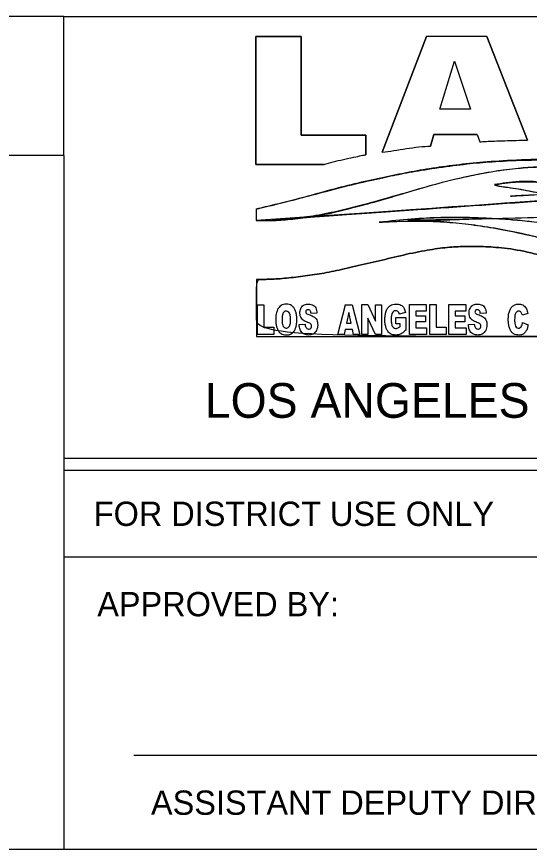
# Model space of a CAD drawing. Extents: x 837 to 1117, y 1316 to 1424.
# Drawn here: x 867.119 to 868.598, y 1399.74 to 1402.14 of the extents above; entities that cross this region are included whole.
import ezdxf

# ---------------------------------------------------------------- set-up
doc = ezdxf.new("R2010")
doc.units = 0
doc.layers.add('BASEMAP', color=7, linetype='Continuous')
doc.layers.add('LLINES', color=7, linetype='Continuous')

# ---------------------------------------------------------------- blocks, each defined once
blk = doc.blocks.new('_U1')
for p, q in [((-1.4473, 0.5842), (-1.6244, 0.5842)), ((-1.6244, 0.5842), (-1.6244, 0.0828)), ((-1.4473, 0.1969), (-1.4473, 0.5842)), ((-1.1295, 0.1307), (-0.9557, 0.5839)), ((-0.9557, 0.5839), (-1.1295, 0.1307)), ((-0.7201, 0.5839), (-0.9557, 0.5839)), ((-0.7201, 0.5839), (-0.5605, 0.1781)), ((-0.5605, 0.1781), (-0.7201, 0.5839)), ((-1.1937, 0.1969), (-1.4473, 0.1969)), ((-1.1937, 0.121), (-1.1937, 0.1969)), ((-0.9275, 0.1996), (-0.9412, 0.155)), ((-0.9412, 0.155), (-0.9275, 0.1996)), ((-0.7577, 0.1996), (-0.9275, 0.1996)), ((-0.9275, 0.1996), (-0.7577, 0.1996)), ((-0.7577, 0.1996), (-0.7467, 0.1714)), ((-0.7577, 0.1996), (-0.7467, 0.1714)), ((-1.6244, 0.0828), (-1.3574, 0.0828)), ((-1.6228, -0.0919), (-1.6228, -0.1365)), ((-1.6228, -0.0919), (-1.6228, -0.1365))]:
    blk.add_line(p, q)
for points in [[(-1.3574, 0.0828), (-1.6244, 0.0828), (-1.6244, 0.5842), (-1.4473, 0.5842), (-1.4473, 0.1969), (-1.1937, 0.1969), (-1.1937, 0.121)], [(-0.904, 0.2994), (-0.8461, 0.4865), (-0.7835, 0.2994), (-0.904, 0.2994)]]:
    blk.add_lwpolyline(points)
blk.add_lwpolyline([(-0.7835, 0.2994), (-0.904, 0.2994), (-0.8461, 0.4865)], close=True)
for points in [[(-0.7467, 0.1714), (-0.7409, 0.1718), (-0.7233, 0.1732), (-0.6924, 0.1746), (-0.6499, 0.1757), (-0.6055, 0.1772), (-0.5744, 0.1778), (-0.5605, 0.1781)], [(-0.7467, 0.1714), (-0.7409, 0.1718), (-0.7233, 0.1732), (-0.6924, 0.1746), (-0.6499, 0.1757), (-0.6055, 0.1772), (-0.5744, 0.1778), (-0.5605, 0.1781)], [(-1.1295, 0.1307), (-1.1149, 0.1326), (-1.0853, 0.1364), (-1.0345, 0.1451), (-0.9863, 0.1518), (-0.9528, 0.1542), (-0.9412, 0.155)], [(-1.1295, 0.1307), (-1.1149, 0.1326), (-1.0853, 0.1364), (-1.0345, 0.1451), (-0.9863, 0.1518), (-0.9528, 0.1542), (-0.9412, 0.155)], [(0.862, 0.0351), (0.8144, 0.0286), (0.7268, 0.0166), (0.5878, 0.0117), (0.4579, 0.0164), (0.3153, 0.0281), (0.181, 0.0458), (0.0233, 0.0686), (-0.1285, 0.0898), (-0.3136, 0.1007), (-0.4878, 0.1049), (-0.6455, 0.0979), (-0.7628, 0.0899), (-0.868, 0.0773), (-0.9701, 0.0628), (-1.064, 0.0445), (-1.1579, 0.0251), (-1.2638, 0.0013), (-1.3727, -0.0283), (-1.4702, -0.0549), (-1.5507, -0.0749), (-1.6006, -0.0866), (-1.6228, -0.0919)], [(-1.6228, -0.0919), (-1.5561, -0.0761), (-1.4734, -0.0554), (-1.3817, -0.0308), (-1.2628, 0.0006), (-1.1454, 0.0275), (-1.0649, 0.0442), (-0.9814, 0.06), (-0.8629, 0.0775), (-0.7589, 0.0894), (-0.6661, 0.0962), (-0.5111, 0.1024), (-0.2859, 0.0985), (-0.1443, 0.0891), (0.0432, 0.0657), (0.1706, 0.0476), (0.3298, 0.0278), (0.4464, 0.0181), (0.5981, 0.0133), (0.7189, 0.0181), (0.862, 0.0351), (-1.6228, -0.0919), (0.862, 0.0351)], [(-1.3574, 0.0828), (-1.3469, 0.0858), (-1.3224, 0.0927), (-1.281, 0.1027), (-1.24, 0.1114), (-1.2103, 0.1177), (-1.1971, 0.1204), (-1.1937, 0.121)], [(-1.3574, 0.0828), (-1.3469, 0.0858), (-1.3224, 0.0927), (-1.281, 0.1027), (-1.24, 0.1114), (-1.2103, 0.1177), (-1.1971, 0.1204), (-1.1937, 0.121)], [(-0.6893, 0.0039), (-0.6489, 0.0103), (-0.5954, 0.0158), (-0.5366, 0.0158), (-0.4643, 0.0069), (-0.3397, -0.01), (-0.2145, -0.0352), (-0.1206, -0.0545), (-0.0156, -0.0758), (0.0777, -0.0926), (0.156, -0.104), (0.2356, -0.1139), (0.3133, -0.1193), (0.4328, -0.1193), (0.5003, -0.1128), (0.5495, -0.1064), (0.591, -0.0996), (0.6293, -0.0912), (0.6734, -0.0739), (0.7303, -0.0551), (0.7937, -0.0344), (0.8668, -0.0105), (0.9177, 0.0048), (0.9599, 0.0174), (1.0152, 0.0322), (1.0666, 0.0451), (1.1275, 0.0585), (1.1733, 0.0677), (1.2254, 0.0756), (1.2908, 0.0827), (1.363, 0.09), (1.4273, 0.0957), (1.5059, 0.1008), (1.5711, 0.1059), (1.6246, 0.1096), (-0.6893, 0.0039), (1.6246, 0.1096)], [(1.6246, 0.1096), (1.6067, 0.1084), (1.5672, 0.1057), (1.5015, 0.1001), (1.432, 0.0965), (1.3604, 0.0899), (1.2931, 0.0829), (1.2297, 0.0766), (1.1752, 0.0686), (1.1224, 0.0574), (1.0695, 0.0462), (1.0138, 0.0317), (0.964, 0.0191), (0.9148, 0.0038), (0.8591, -0.0125), (0.797, -0.0334), (0.7326, -0.0549), (0.6768, -0.071), (0.6325, -0.0922), (0.59, -0.0998), (0.547, -0.107), (0.4943, -0.1137), (0.4157, -0.1221), (0.3271, -0.1207), (0.2347, -0.1148), (0.1563, -0.1041), (0.0725, -0.0924), (-0.0197, -0.0754), (-0.1169, -0.0551), (-0.225, -0.0335), (-0.3386, -0.0075), (-0.4469, 0.0035), (-0.5318, 0.0173), (-0.5938, 0.0168), (-0.6447, 0.0114), (-0.6759, 0.0062), (-0.6893, 0.0039)], [(-1.6228, -0.1365), (-1.599, -0.1369), (-1.555, -0.1377), (-1.4818, -0.1315), (-1.3989, -0.1209), (-1.3107, -0.1036), (-1.2241, -0.0808), (-1.1248, -0.0549), (-1.0062, -0.0178), (-0.8775, 0.0183), (-0.754, 0.0461), (-0.6492, 0.0637), (-0.5652, 0.0707), (-0.5035, 0.0751), (-0.4404, 0.0651), (-0.3485, 0.0503), (-0.224, 0.0304), (-0.1005, 0.0101), (0.0189, -0.0072), (0.1408, -0.0203), (0.2859, -0.0336), (0.4577, -0.0356), (0.6419, -0.0205), (0.7839, 0.0038), (0.8533, 0.0316), (0.862, 0.0351)], [(0.862, 0.0351), (0.8359, 0.0249), (0.6443, -0.0172), (0.4416, -0.0333), (0.286, -0.0316), (0.1309, -0.019), (0.0059, -0.0049), (-0.0795, 0.0072), (-0.2275, 0.0308), (-0.3651, 0.053), (-0.4528, 0.067), (-0.5039, 0.0732), (-0.5544, 0.0714), (-0.6368, 0.0638), (-0.7552, 0.0447), (-0.8679, 0.0195), (-1.007, -0.0188), (-1.1422, -0.0589), (-1.2268, -0.0815), (-1.3034, -0.1009), (-1.4037, -0.1206), (-1.4909, -0.1319), (-1.5515, -0.1365), (-1.6228, -0.1365), (0.862, 0.0351), (-1.6228, -0.1365)], [(-0.6893, 0.0039), (-0.6847, 0.0019), (-0.6743, -0.0027), (-0.6498, -0.0043), (-0.6171, -0.0094), (-0.5747, -0.016), (-0.5259, -0.0263), (-0.4758, -0.0365), (-0.4159, -0.0519), (-0.3581, -0.0657), (-0.2959, -0.0827), (-0.2438, -0.0953), (-0.1863, -0.1087), (-0.1368, -0.1211), (-0.0804, -0.1309), (-0.0319, -0.1418), (0.026, -0.1468), (0.0807, -0.1566), (0.145, -0.1589), (0.2056, -0.1626), (0.2726, -0.1588), (0.3301, -0.1567), (0.3834, -0.1527), (0.4207, -0.1475), (0.456, -0.1427), (0.4886, -0.1369), (0.5244, -0.1311), (0.5679, -0.1216), (0.6186, -0.1112), (0.6718, -0.098), (0.7242, -0.0877), (0.7752, -0.0766), (0.8307, -0.0636), (0.8817, -0.055), (0.9374, -0.0427), (0.9902, -0.0333), (1.0443, -0.0246), (1.0877, -0.0167), (1.1288, -0.0095), (1.1766, -0.0051), (1.2328, 0.002), (1.2932, 0.0072), (1.3499, 0.0118), (1.4167, 0.0153), (1.4938, 0.0159), (1.5658, 0.0229), (1.608, 0.0224), (1.6213, 0.0223)], [(-0.6893, 0.0039), (-0.6753, -0.0015), (-0.6567, -0.0041), (-0.618, -0.0092), (-0.5766, -0.016), (-0.53, -0.0254), (-0.4712, -0.038), (-0.4267, -0.049), (-0.3498, -0.0682), (-0.2983, -0.0818), (-0.2391, -0.0964), (-0.1939, -0.107), (-0.1258, -0.1227), (-0.0898, -0.1295), (-0.0257, -0.1414), (0.0207, -0.1469), (0.0825, -0.1553), (0.1398, -0.1589), (0.2126, -0.1613), (0.2644, -0.1594), (0.3408, -0.1557), (0.3849, -0.1521), (0.4239, -0.1471), (0.4531, -0.1429), (0.4908, -0.1366), (0.5219, -0.1313), (0.5602, -0.1233), (0.6215, -0.1101), (0.6737, -0.098), (0.7206, -0.0883), (0.7781, -0.0758), (0.8269, -0.065), (0.888, -0.0534), (0.9299, -0.0446), (0.9949, -0.0327), (1.046, -0.0241), (1.0918, -0.016), (1.1254, -0.0105), (1.1697, -0.0055), (1.2345, 0.0018), (1.2943, 0.0073), (1.3508, 0.0116), (1.4047, 0.0144), (1.4947, 0.0173), (1.5816, 0.0223), (1.6213, 0.0223), (-0.6893, 0.0039), (1.6213, 0.0223)], [(1.5429, -0.0653), (1.525, -0.0633), (1.4839, -0.0587), (1.4042, -0.0561), (1.2826, -0.0547), (1.1419, -0.0705), (0.9822, -0.1007), (0.8248, -0.1427), (0.6765, -0.1927), (0.5448, -0.2368), (0.4407, -0.2704), (0.35, -0.289), (0.268, -0.3006), (0.1796, -0.297), (0.0628, -0.271), (-0.0577, -0.2383), (-0.1907, -0.2046), (-0.3308, -0.1732), (-0.4575, -0.1522), (-0.5642, -0.1387), (-0.6359, -0.1326), (-0.7096, -0.1284), (-0.7977, -0.1241), (-0.8961, -0.1244), (-1.0163, -0.1299), (-1.0953, -0.1384), (-1.1418, -0.1434)], [(1.5429, -0.0653), (1.4893, -0.0599), (1.4192, -0.0568), (1.304, -0.0568), (1.1259, -0.0749), (0.9988, -0.0989), (0.8255, -0.1445), (0.6548, -0.1999), (0.5497, -0.235), (0.4285, -0.2715), (0.3402, -0.2899), (0.2798, -0.2975), (0.1829, -0.2944), (0.0793, -0.274), (-0.0713, -0.2351), (-0.1816, -0.2074), (-0.3205, -0.1767), (-0.4927, -0.148), (-0.5605, -0.1396), (-0.6398, -0.1327), (-0.7075, -0.1286), (-0.7816, -0.1254), (-0.9041, -0.1254), (-1.0023, -0.1301), (-1.1418, -0.1434), (1.5429, -0.0653), (-1.1418, -0.1434)], [(-1.1418, -0.1434), (-1.107, -0.1414), (-1.038, -0.1377), (-0.9376, -0.1371), (-0.8401, -0.1442), (-0.7439, -0.1565), (-0.6369, -0.1747), (-0.5314, -0.1983), (-0.4104, -0.2274), (-0.2779, -0.2601), (-0.1323, -0.2957), (-0.0039, -0.3215), (0.1104, -0.3371), (0.2173, -0.3456), (0.3265, -0.3487), (0.4461, -0.3371), (0.5769, -0.3159), (0.7114, -0.2661), (0.8406, -0.2172), (0.941, -0.1723), (1.0203, -0.1446), (1.0819, -0.1227), (1.1475, -0.1034), (1.2245, -0.0859), (1.2946, -0.0728), (1.3658, -0.0654), (1.4267, -0.0606), (1.4874, -0.0642), (1.5242, -0.0649), (1.5429, -0.0653)], [(-1.1418, -0.1434), (-1.0374, -0.1385), (-0.9346, -0.1385), (-0.8411, -0.145), (-0.7454, -0.1569), (-0.646, -0.1739), (-0.5208, -0.2011), (-0.4281, -0.2232), (-0.2824, -0.2589), (-0.1227, -0.2967), (0.0102, -0.3226), (0.1024, -0.3352), (0.2195, -0.3447), (0.3307, -0.3464), (0.4287, -0.338), (0.5767, -0.311), (0.7162, -0.2641), (0.8387, -0.2166), (0.9645, -0.1647), (1.0229, -0.1437), (1.0738, -0.1261), (1.1507, -0.1034), (1.2197, -0.0874), (1.3042, -0.0724), (1.3611, -0.0661), (1.4324, -0.0621), (1.4867, -0.0638), (1.5429, -0.0653), (-1.1418, -0.1434), (1.5429, -0.0653)]]:
    blk.add_open_spline(points, degree=3)
at = {"layer": 'LLINES'}
for p, q in [((-1.6222, -0.3677), (-1.6222, -0.5907)), ((-1.5043, -0.4637), (-1.5043, -0.4637)), ((-1.5053, -0.4912), (-1.5055, -0.4911)), ((-1.3852, -0.4987), (-1.4084, -0.5004)), ((-1.0759, -0.5405), (-1.0759, -0.5163)), ((-1.0759, -0.5163), (-1.0378, -0.5163)), ((-1.0388, -0.4968), (-1.0628, -0.5029)), ((-1.0378, -0.5163), (-1.0378, -0.5658)), ((-0.7223, -0.4987), (-0.7456, -0.5004)), ((-0.5592, -0.5001), (-0.5808, -0.5072)), ((-1.455, -0.5441), (-1.4317, -0.5419)), ((-1.0594, -0.5405), (-1.0759, -0.5405)), ((-1.0595, -0.5514), (-1.0594, -0.5514)), ((-1.0594, -0.5514), (-1.0594, -0.5405)), ((-0.7921, -0.5441), (-0.7689, -0.5419)), ((-0.5799, -0.5353), (-0.5583, -0.5448)), ((-1.6222, -0.5907), (1.6237, -0.5907))]:
    blk.add_line(p, q, dxfattribs=at)
for points in [[(-1.618, -0.5829), (-1.618, -0.4662), (-1.5939, -0.4662), (-1.5939, -0.4668), (-1.5939, -0.5537), (-1.5541, -0.5537), (-1.5541, -0.5829), (-1.618, -0.5829)], [(-1.2427, -0.583), (-1.2467, -0.5634), (-1.2747, -0.5634), (-1.279, -0.5827), (-1.304, -0.5828), (-1.2739, -0.466), (-1.2739, -0.4656), (-1.2739, -0.466), (-1.2472, -0.466), (-1.2171, -0.583), (-1.2427, -0.583)], [(-1.1555, -0.583), (-1.1856, -0.5188), (-1.1856, -0.5828), (-1.209, -0.5828), (-1.209, -0.4658), (-1.209, -0.4658), (-1.209, -0.4658), (-1.1861, -0.4656), (-1.1559, -0.5302), (-1.1559, -0.466), (-1.1327, -0.466), (-1.1327, -0.583), (-1.1555, -0.583)], [(-1.0233, -0.5832), (-1.0233, -0.4659), (-0.9572, -0.4659), (-0.9571, -0.4659), (-0.9572, -0.4659), (-0.9572, -0.4908), (-0.9984, -0.4908), (-0.9984, -0.5095), (-0.9603, -0.5095), (-0.9603, -0.5334), (-0.9986, -0.5334), (-0.9986, -0.5561), (-0.956, -0.5561), (-0.956, -0.5832), (-1.0233, -0.5832)], [(-0.9427, -0.5829), (-0.9427, -0.4659), (-0.9183, -0.4659), (-0.9183, -0.5542), (-0.8796, -0.5542), (-0.8796, -0.5829), (-0.9427, -0.5829)], [(-0.8685, -0.5832), (-0.8685, -0.4659), (-0.8024, -0.4659), (-0.8022, -0.4659), (-0.8024, -0.4659), (-0.8024, -0.4908), (-0.8436, -0.4908), (-0.8436, -0.5095), (-0.8055, -0.5095), (-0.8055, -0.5334), (-0.8437, -0.5334), (-0.8437, -0.5561), (-0.8012, -0.5561), (-0.8012, -0.5832), (-0.8685, -0.5832)]]:
    blk.add_lwpolyline(points, dxfattribs=at)
blk.add_lwpolyline([(-1.2695, -0.5381), (-1.2519, -0.5381), (-1.2609, -0.4966)], close=True, dxfattribs=at)
for points in [[(1.6237, -0.1737), (1.5983, -0.1738), (1.5491, -0.1739), (1.4571, -0.1888), (1.3294, -0.2187), (1.1518, -0.2794), (0.9561, -0.3425), (0.7506, -0.3705), (0.5779, -0.3926), (0.4178, -0.4012), (0.2906, -0.4008), (0.1563, -0.396), (0.0001, -0.3778), (-0.1826, -0.346), (-0.3534, -0.3102), (-0.4923, -0.2765), (-0.6042, -0.249), (-0.6984, -0.2398), (-0.7699, -0.2373), (-0.8303, -0.2385), (-0.9006, -0.2439), (-0.9843, -0.2576), (-1.0837, -0.2798), (-1.1773, -0.3031), (-1.27, -0.3237), (-1.3481, -0.3418), (-1.4221, -0.3516), (-1.497, -0.3622), (-1.5633, -0.3666), (-1.6073, -0.3674), (-1.6222, -0.3677), (-1.6222, -0.442), (-1.6222, -0.5164), (-1.6222, -0.5907), (-0.5402, -0.5907), (0.5418, -0.5907), (1.6237, -0.5907), (1.6237, -0.4517), (1.6237, -0.3127), (1.6237, -0.1737)], [(1.6237, -0.1737), (1.5983, -0.1738), (1.5491, -0.1739), (1.4571, -0.1888), (1.3294, -0.2187), (1.1518, -0.2794), (0.9561, -0.3425), (0.7506, -0.3705), (0.5779, -0.3926), (0.4178, -0.4012), (0.2906, -0.4008), (0.1563, -0.396), (0.0001, -0.3778), (-0.1826, -0.346), (-0.3534, -0.3102), (-0.4923, -0.2765), (-0.6042, -0.249), (-0.6984, -0.2398), (-0.7699, -0.2373), (-0.8303, -0.2385), (-0.9006, -0.2439), (-0.9843, -0.2576), (-1.0837, -0.2798), (-1.1773, -0.3031), (-1.27, -0.3237), (-1.3481, -0.3418), (-1.4221, -0.3516), (-1.497, -0.3622), (-1.5633, -0.3666), (-1.6073, -0.3674), (-1.6222, -0.3677)], [(-1.5043, -0.4637), (-1.5015, -0.464), (-1.4941, -0.4646), (-1.484, -0.469), (-1.4758, -0.4774), (-1.4698, -0.4875), (-1.4658, -0.5005), (-1.4638, -0.5164), (-1.4639, -0.5321), (-1.4656, -0.5462), (-1.4686, -0.5578), (-1.4735, -0.568), (-1.4806, -0.5765), (-1.4894, -0.5824), (-1.4989, -0.5848), (-1.5082, -0.5847), (-1.5173, -0.5835), (-1.5255, -0.5798), (-1.5332, -0.5735), (-1.5388, -0.5644), (-1.544, -0.5524), (-1.5462, -0.5397), (-1.5469, -0.5282), (-1.5468, -0.5189), (-1.5459, -0.508), (-1.5439, -0.4964), (-1.5394, -0.4848), (-1.5338, -0.4761), (-1.5265, -0.4695), (-1.5166, -0.4644), (-1.5089, -0.4639), (-1.5043, -0.4637)], [(-1.4084, -0.5004), (-1.4087, -0.4985), (-1.4092, -0.4945), (-1.4114, -0.4893), (-1.4159, -0.4864), (-1.4207, -0.4853), (-1.4255, -0.4864), (-1.4286, -0.49), (-1.4298, -0.4948), (-1.4279, -0.5001), (-1.4217, -0.5039), (-1.4132, -0.5059), (-1.4038, -0.5098), (-1.395, -0.5144), (-1.3884, -0.5215), (-1.3842, -0.5302), (-1.3821, -0.5398), (-1.3824, -0.551), (-1.3848, -0.5619), (-1.3897, -0.5716), (-1.3963, -0.5787), (-1.4046, -0.5833), (-1.4138, -0.5849), (-1.4226, -0.5849), (-1.4309, -0.5835), (-1.4384, -0.5807), (-1.4451, -0.5756), (-1.4499, -0.5677), (-1.453, -0.5584), (-1.4548, -0.5504), (-1.4549, -0.5456), (-1.455, -0.5441)], [(-1.4317, -0.5419), (-1.4316, -0.5434), (-1.431, -0.5479), (-1.4292, -0.5544), (-1.4246, -0.5601), (-1.4185, -0.5625), (-1.412, -0.5611), (-1.4074, -0.5563), (-1.4061, -0.5499), (-1.4074, -0.5429), (-1.4131, -0.5377), (-1.4214, -0.5353), (-1.4306, -0.5318), (-1.4398, -0.5269), (-1.4469, -0.5192), (-1.451, -0.5099), (-1.4525, -0.4993), (-1.4516, -0.4897), (-1.4488, -0.4807), (-1.4444, -0.4736), (-1.4384, -0.468), (-1.4309, -0.465), (-1.4227, -0.464), (-1.4134, -0.4636), (-1.4043, -0.4656), (-1.3957, -0.4703), (-1.3895, -0.4782), (-1.3862, -0.4882), (-1.3855, -0.4952), (-1.3852, -0.4987)], [(-1.0378, -0.5658), (-1.0417, -0.5695), (-1.0487, -0.5761), (-1.0612, -0.5834), (-1.0747, -0.5851), (-1.0882, -0.5843), (-1.1014, -0.5785), (-1.11, -0.5678), (-1.1154, -0.5551), (-1.1185, -0.5406), (-1.1201, -0.524), (-1.1183, -0.5076), (-1.1148, -0.4905), (-1.1077, -0.4774), (-1.0976, -0.4685), (-1.0881, -0.4644), (-1.0762, -0.4636), (-1.0652, -0.464), (-1.056, -0.467), (-1.0489, -0.4723), (-1.0437, -0.4802), (-1.0405, -0.489), (-1.0393, -0.4945), (-1.0388, -0.4968)], [(-0.7456, -0.5004), (-0.7458, -0.4985), (-0.7464, -0.4945), (-0.7486, -0.4893), (-0.7531, -0.4864), (-0.7578, -0.4853), (-0.7627, -0.4864), (-0.7658, -0.49), (-0.7669, -0.4948), (-0.765, -0.5001), (-0.7588, -0.5039), (-0.7504, -0.5059), (-0.741, -0.5098), (-0.7321, -0.5144), (-0.7255, -0.5215), (-0.7213, -0.5302), (-0.7193, -0.5398), (-0.7195, -0.551), (-0.7219, -0.5619), (-0.7269, -0.5716), (-0.7335, -0.5787), (-0.7418, -0.5833), (-0.751, -0.5849), (-0.7598, -0.5849), (-0.768, -0.5835), (-0.7755, -0.5807), (-0.7823, -0.5756), (-0.7871, -0.5677), (-0.7902, -0.5584), (-0.792, -0.5504), (-0.7921, -0.5456), (-0.7921, -0.5441)], [(-0.7689, -0.5419), (-0.7687, -0.5434), (-0.7682, -0.5479), (-0.7663, -0.5544), (-0.7617, -0.5601), (-0.7556, -0.5625), (-0.7492, -0.5611), (-0.7446, -0.5563), (-0.7432, -0.5499), (-0.7445, -0.5429), (-0.7503, -0.5377), (-0.7585, -0.5353), (-0.7677, -0.5318), (-0.7769, -0.5269), (-0.7841, -0.5192), (-0.7882, -0.5099), (-0.7897, -0.4993), (-0.7888, -0.4897), (-0.7859, -0.4807), (-0.7816, -0.4736), (-0.7755, -0.468), (-0.7681, -0.465), (-0.7598, -0.464), (-0.7505, -0.4636), (-0.7414, -0.4656), (-0.7329, -0.4703), (-0.7267, -0.4782), (-0.7233, -0.4882), (-0.7227, -0.4952), (-0.7223, -0.4987)], [(-0.5583, -0.5448), (-0.559, -0.5488), (-0.5605, -0.5579), (-0.5659, -0.5704), (-0.5751, -0.5805), (-0.5869, -0.5853), (-0.5988, -0.5849), (-0.6098, -0.5831), (-0.6199, -0.5772), (-0.6272, -0.5667), (-0.6332, -0.5535), (-0.6356, -0.5372), (-0.6361, -0.5205), (-0.635, -0.5034), (-0.6309, -0.4884), (-0.6241, -0.4764), (-0.6151, -0.4681), (-0.6043, -0.464), (-0.5933, -0.4636), (-0.5834, -0.4649), (-0.5754, -0.4689), (-0.569, -0.4753), (-0.5648, -0.4826), (-0.5614, -0.491), (-0.56, -0.4967), (-0.5592, -0.5001)], [(-1.5055, -0.4911), (-1.507, -0.4912), (-1.5101, -0.4914), (-1.5139, -0.4942), (-1.5175, -0.498), (-1.5196, -0.5033), (-1.5212, -0.5096), (-1.5219, -0.5167), (-1.522, -0.5238), (-1.5221, -0.5304), (-1.5214, -0.5365), (-1.5205, -0.5427), (-1.5186, -0.5489), (-1.5151, -0.554), (-1.5103, -0.5573), (-1.5053, -0.5579), (-1.5, -0.5573), (-1.4947, -0.5534), (-1.4911, -0.5467), (-1.4893, -0.538), (-1.4888, -0.5286), (-1.4886, -0.5186), (-1.4894, -0.5093), (-1.4915, -0.5015), (-1.4951, -0.4955), (-1.4999, -0.4918), (-1.5037, -0.4913), (-1.5053, -0.4912)], [(-1.0628, -0.5029), (-1.0633, -0.5012), (-1.0645, -0.4965), (-1.0696, -0.4902), (-1.0782, -0.4888), (-1.0853, -0.4918), (-1.0906, -0.4985), (-1.0943, -0.51), (-1.0948, -0.5256), (-1.0938, -0.5411), (-1.0892, -0.5533), (-1.0812, -0.5591), (-1.0736, -0.5591), (-1.0674, -0.5572), (-1.0632, -0.5543), (-1.0605, -0.5522), (-1.0595, -0.5514)], [(-0.5808, -0.5072), (-0.5812, -0.5057), (-0.5822, -0.502), (-0.5847, -0.4964), (-0.5893, -0.4921), (-0.5951, -0.4905), (-0.6012, -0.4919), (-0.6069, -0.4978), (-0.6103, -0.5071), (-0.611, -0.5182), (-0.6111, -0.5299), (-0.6101, -0.5404), (-0.6081, -0.5502), (-0.6017, -0.5571), (-0.5921, -0.5585), (-0.5852, -0.553), (-0.5816, -0.5448), (-0.5805, -0.5387), (-0.5799, -0.5353)]]:
    blk.add_open_spline(points, degree=3, dxfattribs=at)

msp = doc.modelspace()

# ---------------------------------------------------------------- linework, layer by layer
at = {"layer": 'BASEMAP'}
for p, q in [((870.7551, 1400.8665), (867.2551, 1400.8665)), ((870.7551, 1400.8323), (867.2551, 1400.8323)), ((870.7551, 1400.5823), (867.2551, 1400.5823)), ((869.4565, 1400.0104), (867.4565, 1400.0104)), ((876.52, 1399.74), (843.52, 1399.74))]:
    msp.add_line(p, q, dxfattribs=at)
for points in [[(867.2552, 1402.14), (865.2552, 1402.14)], [(867.2552, 1402.14), (876.52, 1402.14)], [(867.2552, 1401.74), (867.2552, 1402.14)], [(867.2552, 1401.74), (865.2552, 1401.74)], [(867.2552, 1401.74), (867.2552, 1399.74)]]:
    msp.add_lwpolyline(points, dxfattribs=at)

# ---------------------------------------------------------------- block references
at = {"xscale": 0.7363891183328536, "yscale": 0.7363891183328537}
msp.add_blockref('_U1', (869.0051, 1401.653), dxfattribs=at)

# ---------------------------------------------------------------- texts
at = {"layer": 'LLINES'}
for s, height, p in [('LOS ANGELES COUNTY PUBLIC WORKS', 0.1, (867.6616, 1400.9838)), ('FOR DISTRICT USE ONLY', 0.07, (867.3413, 1400.6722)), ('APPROVED BY:', 0.07, (867.3514, 1400.4117)), ('ASSISTANT DEPUTY DIRECTOR', 0.07, (867.5063, 1399.8396))]:
    msp.add_text(s, height=height, dxfattribs=at).set_placement(p)

doc.saveas('drawing.dxf')
